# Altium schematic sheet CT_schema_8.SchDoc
size 254 x 194 mm
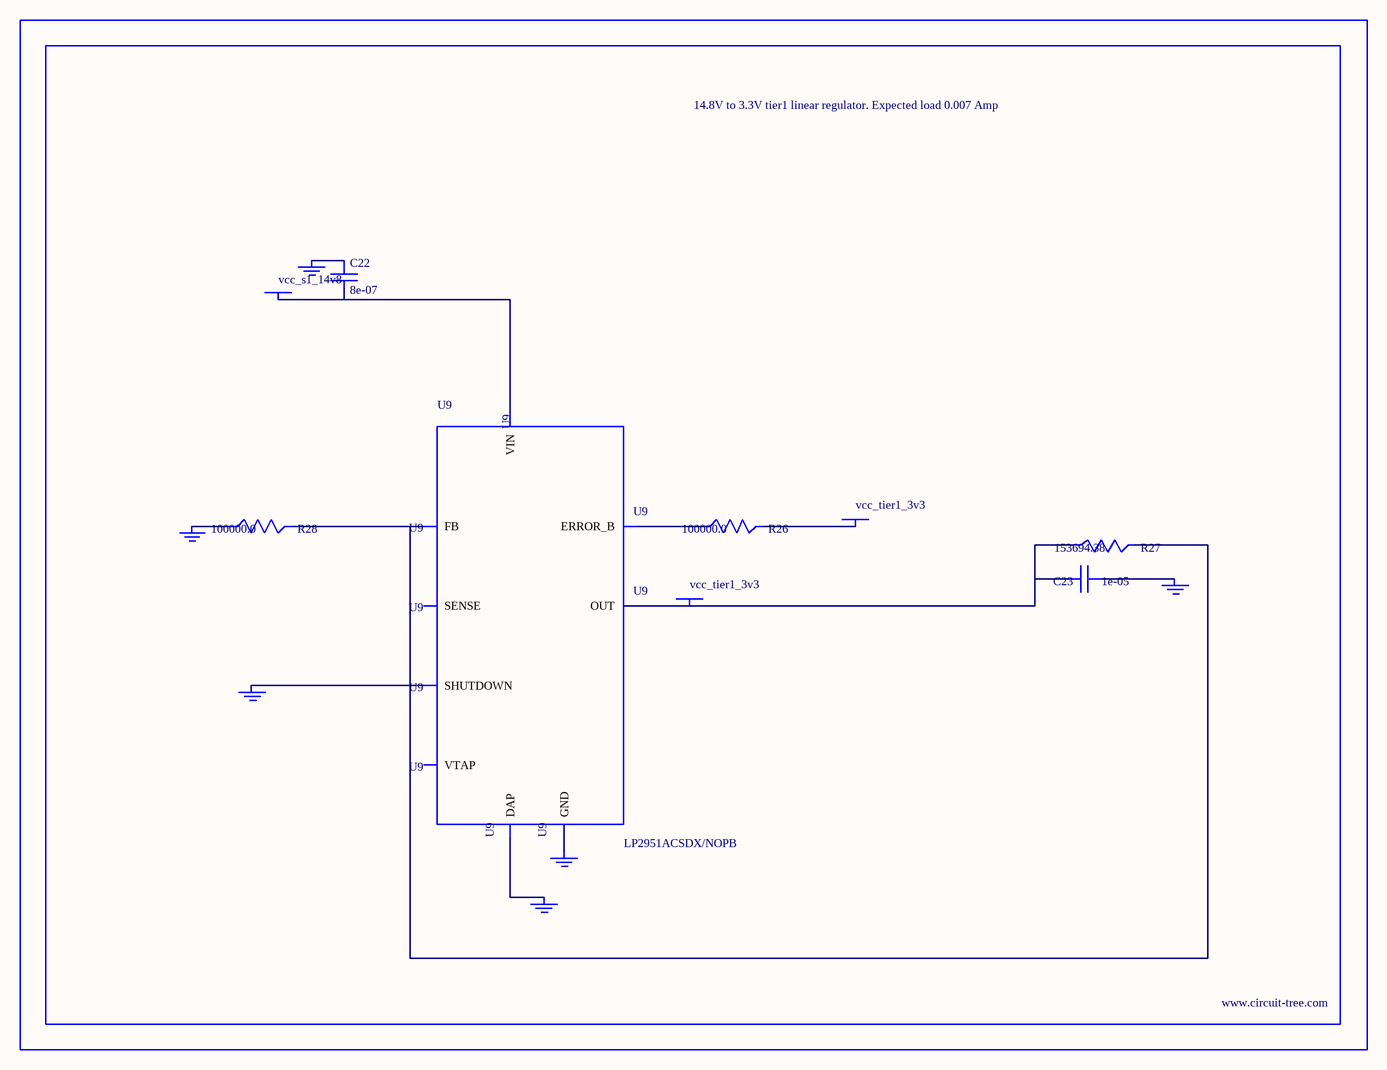
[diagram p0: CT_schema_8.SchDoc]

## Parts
BORDER7  (no value)
C22  8e-07  [R0603]
C23  1e-05  [C1210]
GND_INSTANCE_7_0  (no value)
GND_INSTANCE_7_1  (no value)
GND_INSTANCE_7_2  (no value)
GND_INSTANCE_7_3  (no value)
GND_INSTANCE_7_4  (no value)
GND_INSTANCE_7_5  (no value)
POWER_INSTANCE_7_0  vcc_tier1_3v3
POWER_INSTANCE_7_1  vcc_s1_14v8
POWER_INSTANCE_7_2  vcc_tier1_3v3
R26  100000.0  [R0603]
R27  153694.38  [R0603]
R28  100000.0  [R0603]
U9  LP2951ACSDX/NOPB  [WSON-8]

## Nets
NetC22_1: C22.1 GND_INSTANCE_7_3.0(GND)
NetC22_2: C22.2 POWER_INSTANCE_7_1.0(PWR) U9.8(VIN)
NetC23_1: C23.1 GND_INSTANCE_7_0.0(GND)
NetC23_2: C23.2 POWER_INSTANCE_7_2.0(PWR) R27.1 U9.1(OUT)
NetGND_INSTANCE_7_1_0: GND_INSTANCE_7_1.0(GND) U9.3(SHUTDOWN)
NetGND_INSTANCE_7_2_0: GND_INSTANCE_7_2.0(GND) R28.1
NetGND_INSTANCE_7_4_0: GND_INSTANCE_7_4.0(GND) U9.PAD(DAP)
NetGND_INSTANCE_7_5_0: GND_INSTANCE_7_5.0(GND) U9.4(GND)
NetPOWER_INSTANCE_7_0_0: POWER_INSTANCE_7_0.0(PWR) R26.2
NetR26_1: R26.1 U9.5(ERROR_B)
NetR27_2: R27.2 R28.2 U9.7(FB)

Not connected (* = marked no-connect by the designer): U9 2(SENSE) 6(VTAP)

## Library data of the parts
BORDER7 = BORDER_PAGE7
C22 = C22
C23 = GRM32DR61E106MA12L
GND_INSTANCE_7_0-GND_INSTANCE_7_5 = GND
POWER_INSTANCE_7_0-POWER_INSTANCE_7_2 = PWR
R26 R28 = RC0603JR-07100KL
R27 = R27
